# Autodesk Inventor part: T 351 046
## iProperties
Company: Mayer & Müller AG Schaltgeräte
Created: 2006-10
Part Number: T 351 046
Material: Ag - W75
Document SubType Name: Modeling
Designer: I.Baliuc
Manufacturer: Standard
Standards Organization: Custom
Description: Edelmetalplatte
Density: 10.49 g/cm^3
Mass: 3.94634 g
Surface Area: 8.3286 cm^2
Volume: 0.3762 cm^3
Zweck: Funkenhorn, fest
Author: T.Messerschmitt
Revision Number: 351046
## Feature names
1. Extrusion2
